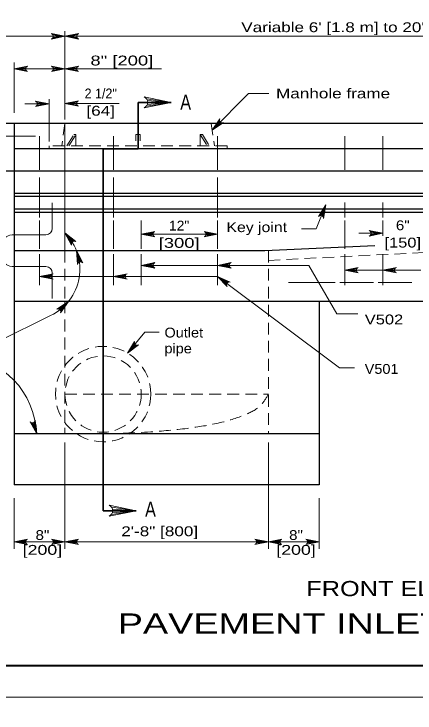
# Model space of a CAD drawing. Extents: x 758.3 to 792.3, y 849.7 to 893.7.
# Drawn here: x 764.9 to 771.26, y 871.44 to 882.51 of the extents above; entities that cross this region are included whole.
import ezdxf
from ezdxf.enums import TextEntityAlignment as Align

# ---------------------------------------------------------------- set-up
doc = ezdxf.new("R2010")
doc.units = 0
doc.header["$LTSCALE"] = 0.062
for name, pattern in [('DOTTED', [1.5, 0.3, -1.2]), ('LONG_DASHED', [7.5, 6, -1.5]), ('MEDIUM_DASHED', [4.5, 3, -1.5])]:
    doc.linetypes.add(name, pattern=pattern)
doc.layers.add('1', color=7, linetype='Continuous', lineweight=13)

msp = doc.modelspace()

# ---------------------------------------------------------------- linework, layer by layer
at = {"layer": '1'}
for p, q in [((765.70775, 880.84192), (765.70775, 882.24175)), ((764.10658, 882.15817), (765.70775, 882.15817)), ((765.51158, 882.12825), (765.70775, 882.15817)), ((765.51383, 882.18533), (765.70775, 882.15817)), ((765.519, 882.14075), (765.70775, 882.15817)), ((765.52042, 882.17192), (765.70775, 882.15817)), ((765.52242, 882.15817), (765.70775, 882.15817)), ((765.90167, 882.18525), (765.70775, 882.15817)), ((765.89508, 882.17183), (765.70775, 882.15817)), ((765.70775, 882.15817), (775.28242, 882.16158)), ((765.89308, 882.15817), (765.70775, 882.15817)), ((765.8965, 882.14067), (765.70775, 882.15817)), ((765.90392, 882.12817), (765.70775, 882.15817)), ((764.9015, 880.9445), (764.9015, 881.74517)), ((765.09525, 881.6685), (764.90133, 881.64133)), ((765.08867, 881.65508), (764.90133, 881.64133)), ((765.45767, 881.64133), (764.90133, 881.64133)), ((765.08667, 881.64133), (764.90133, 881.64133)), ((765.09008, 881.62392), (764.90133, 881.64133)), ((765.09758, 881.61133), (764.90133, 881.64133)), ((765.70775, 881.64133), (765.45767, 881.64133)), ((765.51158, 881.61133), (765.70775, 881.64133)), ((765.51383, 881.6685), (765.70775, 881.64133)), ((765.519, 881.62392), (765.70775, 881.64133)), ((765.52042, 881.65508), (765.70775, 881.64133)), ((765.52242, 881.64133), (765.70775, 881.64133)), ((765.90167, 881.6685), (765.70775, 881.64133)), ((765.89508, 881.65508), (765.70775, 881.64133)), ((765.89308, 881.64133), (765.70775, 881.64133)), ((765.8965, 881.62392), (765.70775, 881.64133)), ((765.90392, 881.61133), (765.70775, 881.64133)), ((767.23617, 881.64133), (765.70775, 881.64133)), ((765.45583, 880.48975), (765.45583, 881.16275)), ((767.0025, 881.16617), (767.39033, 881.11183)), ((767.01567, 881.13925), (767.39033, 881.11183)), ((765.07342, 881.0865), (765.45583, 881.0865)), ((765.25958, 881.0565), (765.45583, 881.0865)), ((765.26192, 881.11367), (765.45583, 881.0865)), ((765.267, 881.06908), (765.45583, 881.0865)), ((765.2685, 881.10025), (765.45583, 881.0865)), ((765.2705, 881.0865), (765.45583, 881.0865)), ((765.90167, 881.11975), (765.70775, 881.09258)), ((765.89508, 881.10633), (765.70775, 881.09258)), ((765.70775, 881.09258), (766.56567, 881.09258)), ((765.89308, 881.09258), (765.70775, 881.09258)), ((765.8965, 881.07517), (765.70775, 881.09258)), ((765.90392, 881.06258), (765.70775, 881.09258)), ((766.998, 881.05192), (767.39033, 881.11183)), ((767.01283, 881.077), (767.39033, 881.11183)), ((767.01967, 881.11183), (767.39033, 881.11183)), ((768.15933, 880.82525), (768.04142, 880.669)), ((768.16417, 880.81117), (768.04142, 880.669)), ((765.70775, 880.77825), (765.70775, 878.76267)), ((768.1725, 880.8), (768.04142, 880.669)), ((768.18725, 880.79017), (768.04142, 880.669)), ((768.20133, 880.7865), (768.04142, 880.669)), ((765.23792, 880.57667), (764.21308, 880.57667)), ((765.30458, 880.57667), (765.30458, 880.04158)), ((766.47808, 880.57667), (766.47808, 880.04158)), ((768.12658, 880.57667), (768.12658, 880.04158)), ((770.14233, 880.57667), (770.14233, 880.04158)), ((770.74708, 880.57667), (770.74708, 880.04158)), ((765.30458, 879.92108), (765.30458, 879.287)), ((766.47808, 879.92108), (766.47808, 879.287)), ((768.12658, 879.92108), (768.12658, 879.287)), ((765.50617, 879.51842), (765.50617, 879.11533)), ((769.74567, 879.31542), (769.84225, 879.48883)), ((769.76008, 879.318), (769.84225, 879.48883)), ((769.77758, 879.31517), (769.84225, 879.48883)), ((769.78975, 879.3085), (769.84225, 879.48883)), ((769.8, 879.29758), (769.84225, 879.48883)), ((770.14233, 879.52792), (770.14233, 879.287)), ((770.74708, 879.52792), (770.74708, 879.287)), ((765.30458, 879.239), (765.30458, 878.7935)), ((766.47808, 879.239), (766.47808, 878.7935)), ((766.91717, 879.239), (766.91717, 878.7935)), ((768.12658, 879.239), (768.12658, 878.7935)), ((770.14233, 879.239), (770.14233, 878.7935)), ((770.74708, 879.239), (770.74708, 878.99892)), ((765.8275, 878.901), (765.70767, 879.04242)), ((765.81642, 878.88717), (765.70767, 879.04242)), ((765.81167, 878.87333), (765.70767, 879.04242)), ((765.83925, 878.90833), (765.70767, 879.04242)), ((765.85375, 878.912), (765.70767, 879.04242)), ((767.11108, 879.0515), (766.91717, 879.02442)), ((767.1045, 879.03808), (766.91717, 879.02442)), ((767.93283, 879.0515), (768.12675, 879.02442)), ((767.93942, 879.03808), (768.12675, 879.02442)), ((770.36467, 879.0375), (770.74708, 879.0375)), ((770.55083, 879.0075), (770.74708, 879.0375)), ((770.55317, 879.06467), (770.74708, 879.0375)), ((770.55833, 879.02008), (770.74708, 879.0375)), ((770.55975, 879.05125), (770.74708, 879.0375)), ((770.56175, 879.0375), (770.74708, 879.0375)), ((764.9015, 879.01458), (765.40542, 879.01458)), ((767.1025, 879.02442), (766.91717, 879.02442)), ((767.10592, 879.007), (766.91717, 879.02442)), ((767.11333, 878.99442), (766.91717, 879.02442)), ((767.9305, 878.99442), (768.12675, 879.02442)), ((767.938, 879.007), (768.12675, 879.02442)), ((767.94142, 879.02442), (768.12675, 879.02442)), ((765.30458, 878.70917), (765.30458, 878.21558)), ((765.93942, 878.58408), (765.89008, 878.76267)), ((765.9235, 878.57617), (765.89008, 878.76267)), ((765.91342, 878.56558), (765.89008, 878.76267)), ((765.95317, 878.58583), (765.89008, 878.76267)), ((765.96783, 878.583), (765.89008, 878.76267)), ((766.47808, 878.70917), (766.47808, 878.21558)), ((766.91717, 878.70917), (766.91717, 878.21558)), ((768.12658, 878.70917), (768.12658, 878.21558)), ((770.14233, 878.70917), (770.14233, 878.21558)), ((770.74708, 878.70917), (770.74708, 878.21558)), ((764.9015, 878.51083), (765.40542, 878.51083)), ((767.11108, 878.55683), (766.91717, 878.52975)), ((767.1045, 878.54342), (766.91717, 878.52975)), ((767.1025, 878.52975), (766.91717, 878.52975)), ((767.10592, 878.51225), (766.91717, 878.52975)), ((767.11333, 878.49975), (766.91717, 878.52975)), ((768.3205, 878.55683), (768.12658, 878.52975)), ((768.31392, 878.54342), (768.12658, 878.52975)), ((768.31192, 878.52975), (768.12658, 878.52975)), ((768.31542, 878.51225), (768.12658, 878.52975)), ((768.32283, 878.49975), (768.12658, 878.52975)), ((770.33625, 878.47992), (770.14233, 878.45283)), ((770.94092, 878.47992), (770.74708, 878.45283)), ((765.4985, 878.38108), (765.30458, 878.35392)), ((765.49192, 878.36767), (765.30458, 878.35392)), ((765.50617, 878.41008), (765.50617, 878.007)), ((766.672, 878.38108), (766.47808, 878.35392)), ((766.66542, 878.36767), (766.47808, 878.35392)), ((770.32967, 878.4665), (770.14233, 878.45283)), ((770.32767, 878.45283), (770.14233, 878.45283)), ((770.33108, 878.43542), (770.14233, 878.45283)), ((770.3385, 878.42283), (770.14233, 878.45283)), ((770.93442, 878.4665), (770.74708, 878.45283)), ((770.93242, 878.45283), (770.74708, 878.45283)), ((770.93583, 878.43542), (770.74708, 878.45283)), ((770.94325, 878.42283), (770.74708, 878.45283)), ((765.48992, 878.35392), (765.30458, 878.35392)), ((765.49333, 878.3365), (765.30458, 878.35392)), ((765.50083, 878.324), (765.30458, 878.35392)), ((766.66342, 878.35392), (766.47808, 878.35392)), ((766.66683, 878.3365), (766.47808, 878.35392)), ((766.67425, 878.324), (766.47808, 878.35392)), ((768.2785, 878.24742), (768.12683, 878.35392)), ((768.27125, 878.23117), (768.12683, 878.35392)), ((768.27008, 878.21667), (768.12683, 878.35392)), ((768.288, 878.2575), (768.12683, 878.35392)), ((768.30108, 878.26467), (768.12683, 878.35392)), ((769.622, 878.25883), (769.25008, 878.25883)), ((769.9915, 878.25883), (769.62467, 878.25883)), ((770.59758, 878.25883), (770.06283, 878.25883)), ((771.20883, 878.25883), (770.67408, 878.25883)), ((765.6, 877.8415), (765.76175, 877.9565)), ((765.61408, 877.83767), (765.76175, 877.9565)), ((765.62867, 877.8275), (765.76175, 877.9565)), ((765.63675, 877.81633), (765.76175, 877.9565)), ((765.64142, 877.80208), (765.76175, 877.9565)), ((764.376, 877.19192), (765.47942, 877.73608)), ((766.80858, 877.29992), (766.70058, 877.13658)), ((766.81425, 877.28608), (766.70058, 877.13658)), ((766.82325, 877.2755), (766.70058, 877.13658)), ((766.83858, 877.26658), (766.70058, 877.13658)), ((766.85292, 877.26383), (766.70058, 877.13658)), ((765.21875, 876.04542), (765.26, 875.86042)), ((765.2285, 876.05633), (765.26, 875.86042)), ((765.17483, 876.03667), (765.26, 875.86042)), ((765.18958, 876.0345), (765.26, 875.86042)), ((765.20325, 876.03683), (765.26, 875.86042)), ((765.70775, 875.72392), (765.70775, 874.0415)), ((768.93292, 875.72392), (768.93292, 874.0415)), ((764.9015, 874.84175), (764.9015, 874.0415)), ((769.73917, 874.84175), (769.73917, 874.0415)), ((766.44367, 874.58267), (766.836, 874.64258)), ((766.44817, 874.69683), (766.836, 874.64258)), ((766.4585, 874.60775), (766.836, 874.64258)), ((766.46133, 874.67), (766.836, 874.64258)), ((766.46533, 874.64258), (766.836, 874.64258)), ((765.09533, 874.17733), (764.9015, 874.15017)), ((765.08883, 874.16392), (764.9015, 874.15017)), ((765.51383, 874.17733), (765.70775, 874.15017)), ((765.52042, 874.16392), (765.70775, 874.15017)), ((765.90167, 874.17733), (765.70775, 874.15017)), ((765.89508, 874.16392), (765.70775, 874.15017)), ((768.739, 874.17733), (768.93292, 874.15017)), ((768.74558, 874.16392), (768.93292, 874.15017)), ((769.12683, 874.17733), (768.93292, 874.15017)), ((769.12025, 874.16392), (768.93292, 874.15017)), ((769.54533, 874.17733), (769.73917, 874.15017)), ((769.55183, 874.16392), (769.73917, 874.15017)), ((765.08683, 874.15017), (764.9015, 874.15017)), ((765.09025, 874.13275), (764.9015, 874.15017)), ((765.09767, 874.12017), (764.9015, 874.15017)), ((765.51158, 874.12017), (765.70775, 874.15017)), ((765.519, 874.13275), (765.70775, 874.15017)), ((765.52242, 874.15017), (765.70775, 874.15017)), ((765.70775, 874.15017), (767.99217, 874.15017)), ((765.89308, 874.15017), (765.70775, 874.15017)), ((765.8965, 874.13275), (765.70775, 874.15017)), ((765.90392, 874.12017), (765.70775, 874.15017)), ((767.99217, 874.15017), (768.93292, 874.15017)), ((768.73675, 874.12017), (768.93292, 874.15017)), ((768.74417, 874.13275), (768.93292, 874.15017)), ((768.74758, 874.15017), (768.93292, 874.15017)), ((769.11825, 874.15017), (768.93292, 874.15017)), ((769.12167, 874.13275), (768.93292, 874.15017)), ((769.12908, 874.12017), (768.93292, 874.15017)), ((769.543, 874.12017), (769.73917, 874.15017)), ((769.55042, 874.13275), (769.73917, 874.15017)), ((769.55383, 874.15017), (769.73917, 874.15017))]:
    msp.add_line(p, q, dxfattribs=at)
at = {"layer": '1', "lineweight": 35}
for p, q in [((766.86683, 881.11183), (766.86683, 880.77825)), ((767.39033, 881.11183), (766.86683, 881.11183)), ((766.86683, 880.86817), (766.86683, 880.67875)), ((766.86683, 880.77825), (766.86683, 880.37508)), ((766.86683, 880.37508), (766.3125, 880.37508)), ((766.3125, 879.03675), (766.3125, 880.37508)), ((766.3125, 878.76267), (766.3125, 879.03675)), ((766.3125, 876.837), (766.3125, 878.76267)), ((766.3125, 874.64258), (766.836, 874.64258))]:
    msp.add_line(p, q, dxfattribs=at)
at = {"layer": '1', "lineweight": 25}
for p, q in [((779.047, 880.77825), (761.99533, 880.77825)), ((764.9015, 880.77825), (764.9015, 877.9565)), ((766.37083, 880.37508), (764.9015, 880.37508)), ((771.90542, 880.37508), (766.86683, 880.37508)), ((776.4595, 880.02242), (764.69333, 880.02242)), ((776.06025, 879.41775), (764.9015, 879.41775)), ((776.06025, 879.36733), (764.9015, 879.36733)), ((768.87458, 878.76267), (770.62117, 878.84508)), ((764.9015, 878.76267), (768.87458, 878.76267)), ((764.9015, 877.9565), (764.9015, 875.05417)), ((776.08867, 877.9565), (764.9015, 877.9565)), ((769.73917, 875.86042), (764.9015, 875.86042))]:
    msp.add_line(p, q, dxfattribs=at)
at = {"layer": '1', "linetype": 'MEDIUM_DASHED'}
for p, q in [((765.70775, 880.77825), (765.65733, 880.4255)), ((768.02583, 880.77825), (768.07625, 880.4255)), ((765.73742, 880.4255), (765.8465, 880.60183)), ((765.77067, 880.4255), (765.87983, 880.60183)), ((765.87983, 880.60183), (765.8465, 880.60183)), ((765.87983, 880.60183), (765.87983, 880.4255)), ((767.88692, 880.60183), (767.85367, 880.60183)), ((767.85367, 880.60183), (767.85367, 880.4255)), ((767.85367, 880.60183), (767.96283, 880.4255)), ((767.88692, 880.60183), (767.99608, 880.4255)), ((768.27783, 880.4255), (765.45583, 880.4255)), ((765.45583, 880.37508), (765.45583, 880.4255)), ((768.27783, 880.37508), (768.27783, 880.4255)), ((768.93292, 878.60875), (774.64925, 878.89358)), ((765.70775, 878.76267), (765.70775, 877.93525)), ((768.93292, 878.76267), (768.93292, 875.86042)), ((765.70775, 877.9565), (765.70775, 875.86042)), ((765.70775, 876.49025), (768.93292, 876.49025))]:
    msp.add_line(p, q, dxfattribs=at)
at = {"layer": '1', "linetype": 'DOTTED'}
for p, q in [((766.8335, 880.60183), (766.8335, 880.4255)), ((766.90008, 880.60183), (766.8335, 880.60183)), ((766.90008, 880.60183), (766.90008, 880.4255))]:
    msp.add_line(p, q, dxfattribs=at)
at = {"layer": '1', "linetype": 'LONG_DASHED'}
for points in [[(758.3205, 871.68817), (792.3205, 871.68817), (792.3205, 893.68817), (758.3205, 893.68817)], [(758.3205, 849.68817), (792.3205, 849.68817), (792.3205, 871.68817), (758.3205, 871.68817)]]:
    msp.add_lwpolyline(points, close=True, dxfattribs=at)
at = {"layer": '1', "lineweight": 25}
for points in [[(791.8205, 872.18817), (760.3205, 872.18817), (760.3205, 893.18817)], [(776.06025, 879.66967), (770.09983, 879.66967), (764.9015, 879.66967)], [(776.06025, 879.61933), (770.08125, 879.61933), (764.9015, 879.61933)], [(769.73917, 877.9565), (769.73917, 875.05417), (764.9015, 875.05417)]]:
    msp.add_lwpolyline(points, dxfattribs=at)
at = {"layer": '1', "lineweight": 40}
msp.add_lwpolyline([(760.3205, 893.18817), (791.8205, 893.18817), (791.8205, 872.18817), (760.3205, 872.18817)], close=True, dxfattribs=at)
at = {"layer": '1'}
for points in [[(765.49358, 882.11533), (765.70775, 882.15817), (765.49358, 882.201)], [(765.92192, 882.11533), (765.70775, 882.15817), (765.92192, 882.201)], [(765.1155, 881.5985), (764.90133, 881.64133), (765.1155, 881.68417)], [(765.49358, 881.5985), (765.70775, 881.64133), (765.49358, 881.68417)], [(765.92192, 881.5985), (765.70775, 881.64133), (765.92192, 881.68417)], [(768.04142, 880.669), (768.62, 881.25033), (768.9375, 881.25033)], [(765.92192, 881.04975), (765.70775, 881.09258), (765.92192, 881.13542)], [(766.962, 881.02617), (767.39033, 881.11183), (766.962, 881.19758)], [(765.24158, 881.04367), (765.45583, 881.0865), (765.24158, 881.12933)], [(768.22317, 880.79017), (768.04142, 880.669), (768.16258, 880.85075)], [(769.84225, 879.48883), (769.68925, 879.11075), (769.45592, 879.11075)], [(769.72733, 879.303), (769.84225, 879.48883), (769.80767, 879.27317)], [(765.8135, 878.85133), (765.70767, 879.04242), (765.87883, 878.90667)], [(767.13133, 878.98158), (766.91717, 879.02442), (767.13133, 879.06725)], [(767.91258, 878.98158), (768.12675, 879.02442), (767.91258, 879.06725)], [(770.53292, 878.99467), (770.74708, 879.0375), (770.53292, 879.08033)], [(766.91717, 879.02442), (767.735, 879.02442), (768.12675, 879.02442)], [(765.90583, 878.54483), (765.89008, 878.76267), (765.98842, 878.56767)], [(767.13133, 878.48692), (766.91717, 878.52975), (767.13133, 878.57258)], [(769.57575, 878.52975), (768.12658, 878.52975), (766.91717, 878.52975)], [(768.34075, 878.48692), (768.12658, 878.52975), (768.34075, 878.57258)], [(769.57575, 878.52975), (770.01875, 877.7625), (770.34942, 877.7625)], [(770.3565, 878.41), (770.14233, 878.45283), (770.3565, 878.49567)], [(770.96125, 878.41), (770.74708, 878.45283), (770.96125, 878.49567)], [(765.51875, 878.31108), (765.30458, 878.35392), (765.51875, 878.39675)], [(766.69225, 878.31108), (766.47808, 878.35392), (766.69225, 878.39675)], [(770.14233, 878.45283), (770.74708, 878.45283), (771.35175, 878.45283)], [(765.30458, 878.35392), (766.47808, 878.35392), (768.12683, 878.35392)], [(768.27742, 878.19583), (768.12683, 878.35392), (768.32667, 878.26592)], [(768.12683, 878.35392), (770.0625, 876.90608), (770.29575, 876.90608)], [(765.57817, 877.83825), (765.76175, 877.9565), (765.63775, 877.77667)], [(766.70058, 877.13658), (766.97508, 877.47275), (767.20192, 877.47275)], [(766.87442, 877.26883), (766.70058, 877.13658), (766.81017, 877.3255)], [(765.23517, 876.07742), (765.26, 875.86042), (765.15367, 876.05117)], [(766.40767, 874.55692), (766.836, 874.64258), (766.40767, 874.72825)], [(765.11567, 874.10733), (764.9015, 874.15017), (765.11567, 874.193)], [(765.49358, 874.10733), (765.70775, 874.15017), (765.49358, 874.193)], [(765.92192, 874.10733), (765.70775, 874.15017), (765.92192, 874.193)], [(768.71875, 874.10733), (768.93292, 874.15017), (768.71875, 874.193)], [(769.14708, 874.10733), (768.93292, 874.15017), (769.14708, 874.193)], [(769.525, 874.10733), (769.73917, 874.15017), (769.525, 874.193)], [(764.9015, 874.15017), (765.402, 874.15017), (765.70775, 874.15017)], [(768.93292, 874.15017), (769.4865, 874.15017), (769.73917, 874.15017)]]:
    msp.add_lwpolyline(points, dxfattribs=at)
at = {"layer": '1', "lineweight": 35}
msp.add_lwpolyline([(766.3125, 874.64258), (766.3125, 876.57383), (766.3125, 876.837)], dxfattribs=at)
at = {"layer": '1'}
for centre, radius, start, end in [((765.47629, 882.15824), 0.04623, 292.08605, 67.91218), ((765.93922, 882.15818), 0.04623, 112.08782, 247.91395), ((765.13283, 881.6414), 0.04623, 112.08782, 247.91395), ((765.47629, 881.6414), 0.04623, 292.08605, 67.91218), ((765.93922, 881.6414), 0.04623, 112.08782, 247.91395), ((765.93922, 881.09265), 0.04623, 112.08782, 247.91395), ((766.92739, 881.11197), 0.09245, 292.08605, 67.91218), ((765.22433, 881.08656), 0.04623, 292.08605, 67.91218), ((768.20506, 880.8327), 0.04623, 157.09783, 292.92396), ((769.76152, 879.27187), 0.04623, 1.67209, 137.49822), ((765.13418, 878.46953), 0.81061, 295.20482, 44.96671), ((767.14865, 879.02446), 0.04623, 112.08782, 247.91395), ((767.89525, 879.02446), 0.04623, 292.08605, 67.91218), ((770.51559, 879.03756), 0.04623, 292.08605, 67.91218), ((765.85738, 878.86583), 0.04623, 62.36823, 198.19436), ((765.95174, 878.53961), 0.04623, 37.53266, 173.35879), ((767.14865, 878.52976), 0.04623, 112.08782, 247.91395), ((768.35809, 878.52976), 0.04623, 112.08782, 247.91395), ((770.3738, 878.45287), 0.04623, 112.08782, 247.91395), ((770.97852, 878.45287), 0.04623, 112.08782, 247.91395), ((765.53608, 878.35401), 0.04623, 112.08782, 247.91395), ((766.70953, 878.35401), 0.04623, 112.08782, 247.91395), ((768.31625, 878.22095), 0.04623, 77.00133, 212.82746), ((765.59558, 877.7954), 0.04623, 336.18293, 112.00906), ((766.85371, 877.31016), 0.04623, 160.66007, 296.48619), ((763.93528, 875.79981), 1.32607, 2.61776, 84.30527), ((765.18909, 876.08072), 0.04623, 219.90677, 355.7329), ((766.37307, 874.6427), 0.09245, 292.08605, 67.91218), ((765.13294, 874.15023), 0.04623, 112.08782, 247.91395), ((765.47629, 874.15023), 0.04623, 292.08605, 67.91218), ((765.93922, 874.15023), 0.04623, 112.08782, 247.91395), ((768.70144, 874.15023), 0.04623, 292.08605, 67.91218), ((769.16437, 874.15023), 0.04623, 112.08782, 247.91395), ((769.50773, 874.15023), 0.04623, 292.08605, 67.91218)]:
    msp.add_arc(centre, radius, start, end, dxfattribs=at)
for centre, major_axis, start_param, end_param in [((765.4054, 879.11532), (0.10079, 0), 4.71238903, 6.28318531), ((764.90147, 878.7627), (0.25196, 0), 1.57079628, 4.71238898), ((765.4054, 878.41009), (0.10079, 0), 6.28318531, 7.85398159)]:
    msp.add_ellipse(centre, major_axis=major_axis, ratio=0.999895, start_param=start_param, end_param=end_param, dxfattribs=at)
at = {"layer": '1', "linetype": 'MEDIUM_DASHED'}
for major_axis in [(0.75589, 0), (0.60472, 0)]:
    msp.add_ellipse((766.31247, 876.49022), major_axis=major_axis, ratio=0.999895, dxfattribs=at)
msp.add_spline([(768.93292, 876.49025), (768.81517, 876.3165), (768.57967, 876.17058), (768.22617, 876.05233), (767.75508, 875.96208), (767.16583, 875.8995), (766.37083, 875.86042)], degree=3, dxfattribs=at)

# ---------------------------------------------------------------- texts
at = {"layer": '1'}
for s, height, width, p in [("Variable 6' [1.8 m] to 20' [6.0 m]", 0.156, 1.3, (768.5025, 882.22417)), ('Manhole frame', 0.156, 1.3, (769.05408, 881.175)), ('A', 0.24, 0.8, (767.53533, 880.99517)), ('Key joint', 0.156, 1.2, (768.26792, 879.05692)), ('V502', 0.156, 1.25, (770.461, 877.5945)), ('Outlet', 0.156, 1.1, (767.28533, 877.38692)), ('pipe', 0.156, 1.1, (767.28533, 877.13575)), ('V501', 0.156, 1.1, (770.45983, 876.81108)), ('A', 0.24, 0.8, (766.97783, 874.54675)), ('2\'-8" [800]', 0.156, 1.3, (766.60033, 874.2395)), ('FRONT ELEVATION', 0.24, 1.25, (769.53367, 873.28975)), ("PAVEMENT INLETS (6' [1.8 m] to 20' [6.0 m])", 0.32, 1.4, (766.54458, 872.69542))]:
    msp.add_text(s, height=height, dxfattribs=dict(at, width=width)).set_placement(p)
for s, width, p in [('8" [200]', 1.4, (766.60958, 881.69667)), ('2 1/2"', 0.95, (766.27425, 881.17467)), ('[64]', 1.3, (766.27429, 880.90067)), ('12"', 1.05, (767.51796, 879.08183)), ('6"', 1.15, (771.06296, 879.08642)), ('[300]', 1.4, (767.51804, 878.80783)), ('[150]', 1.25, (771.06304, 878.81242)), ('8"', 1.15, (765.35021, 874.17933)), ('8"', 1.15, (769.37037, 874.17925)), ('[200]', 1.35, (765.35029, 873.94467)), ('[200]', 1.35, (769.37046, 873.94458))]:
    msp.add_text(s, height=0.156, dxfattribs=dict(at, width=width)).set_placement(p, align=Align.CENTER)

doc.saveas('drawing.dxf')
